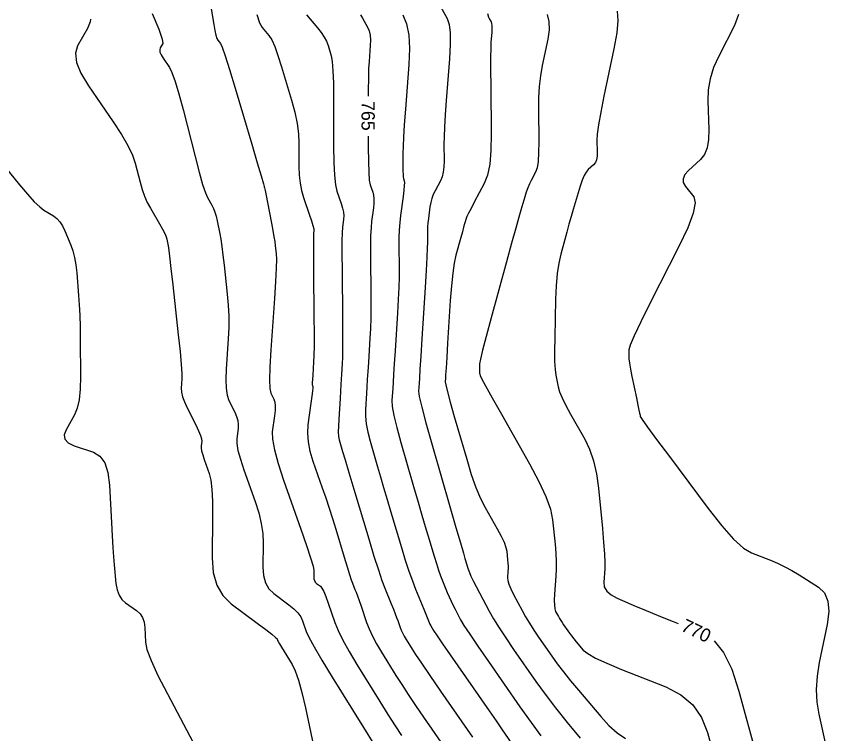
# Model space of a CAD drawing. Extents: x 2082232 to 2083549, y 592624 to 593832.
# Drawn here: x 2082859.4 to 2082902.15, y 592954.31 to 592992.08 of the extents above; entities that cross this region are included whole.
import ezdxf

# ---------------------------------------------------------------- set-up
doc = ezdxf.new("R2010")
doc.units = 0
doc.layers.add('DT_X_Contour_Major', color=7, linetype='Continuous')
doc.layers.add('DT_X_Contour_Minor', color=7, linetype='Continuous')

msp = doc.modelspace()

# ---------------------------------------------------------------- linework, layer by layer
at = {"layer": 'DT_X_Contour_Major'}
for points in [[(2082863.303, 592991.929), (2082863.288, 592991.791), (2082863.144, 592991.432), (2082862.623, 592990.518), (2082862.512, 592990.129), (2082862.572, 592989.649), (2082862.802, 592989.077), (2082863.203, 592988.414), (2082864.497, 592986.522), (2082864.934, 592985.854), (2082865.273, 592985.269), (2082865.516, 592984.767), (2082865.661, 592984.347), (2082865.918, 592983.339), (2082866.024, 592982.969), (2082866.151, 592982.618), (2082866.298, 592982.285), (2082866.465, 592981.97), (2082866.937, 592981.153), (2082867.094, 592980.873), (2082867.212, 592980.645), (2082867.29, 592980.47), (2082867.329, 592980.348), (2082867.379, 592980.092), (2082867.409, 592979.885), (2082867.462, 592979.457), (2082867.537, 592978.807), (2082867.635, 592977.936), (2082867.927, 592975.319), (2082868.021, 592974.437), (2082868.084, 592973.755), (2082868.118, 592973.272), (2082868.12, 592972.988), (2082868.087, 592972.499), (2082868.098, 592972.296), (2082868.153, 592972.056), (2082868.253, 592971.777), (2082868.399, 592971.461), (2082868.847, 592970.566), (2082868.992, 592970.261), (2082869.092, 592970.018), (2082869.148, 592969.836), (2082869.158, 592969.716), (2082869.125, 592969.476), (2082869.126, 592969.363), (2082869.155, 592969.203), (2082869.212, 592968.997), (2082869.295, 592968.744), (2082869.556, 592968.007), (2082869.64, 592967.661), (2082869.698, 592967.177), (2082869.729, 592966.554), (2082869.733, 592965.793), (2082869.707, 592963.578), (2082869.763, 592962.804), (2082869.949, 592962.141), (2082870.265, 592961.591), (2082870.712, 592961.154), (2082872.076, 592960.136), (2082872.525, 592959.798), (2082872.849, 592959.548), (2082873.048, 592959.385), (2082873.121, 592959.31), (2082873.15, 592959.225), (2082873.18, 592959.165), (2082873.247, 592959.048), (2082873.351, 592958.874), (2082873.493, 592958.644), (2082873.92, 592957.953), (2082874.084, 592957.617), (2082874.254, 592957.127), (2082874.431, 592956.482), (2082874.615, 592955.683), (2082875.114, 592953.345)], [(2082877.522, 592992.148), (2082877.626, 592991.972), (2082877.884, 592991.506), (2082877.966, 592991.315), (2082878.017, 592991.089), (2082878.038, 592990.829), (2082878.029, 592990.536), (2082877.965, 592989.707), (2082877.944, 592989.33), (2082877.929, 592988.823), (2082877.92, 592988.183), (2082877.919, 592987.871)], [(2082891.025, 592992.35), (2082891.055, 592991.864), (2082890.996, 592991.2), (2082890.846, 592990.358), (2082890.325, 592987.877), (2082890.156, 592987.033), (2082890.037, 592986.364), (2082889.969, 592985.869), (2082889.952, 592985.549), (2082889.976, 592984.927), (2082889.97, 592984.711), (2082889.935, 592984.528), (2082889.871, 592984.38), (2082889.778, 592984.265), (2082889.491, 592984.006), (2082889.384, 592983.879), (2082889.279, 592983.692), (2082889.175, 592983.447), (2082889.074, 592983.142), (2082888.805, 592982.251), (2082888.702, 592981.904), (2082888.595, 592981.533), (2082888.483, 592981.137), (2082888.367, 592980.717), (2082888.053, 592979.563), (2082887.948, 592979.089), (2082887.868, 592978.534), (2082887.812, 592977.898), (2082887.782, 592977.18), (2082887.734, 592975.157), (2082887.724, 592974.465), (2082887.73, 592973.905), (2082887.753, 592973.478), (2082887.792, 592973.184), (2082887.918, 592972.577), (2082887.994, 592972.316), (2082888.128, 592971.988), (2082888.32, 592971.595), (2082888.57, 592971.135), (2082889.315, 592969.82), (2082889.569, 592969.289), (2082889.773, 592968.681), (2082889.927, 592967.997), (2082890.031, 592967.237), (2082890.242, 592965.109), (2082890.309, 592964.377), (2082890.351, 592963.78), (2082890.369, 592963.317), (2082890.363, 592962.988), (2082890.312, 592962.289), (2082890.343, 592962.039), (2082890.471, 592961.815), (2082890.698, 592961.617), (2082891.024, 592961.444), (2082892.022, 592961.016), (2082892.424, 592960.846), (2082892.881, 592960.657), (2082893.392, 592960.449), (2082893.959, 592960.222), (2082894.238, 592960.11)], [(2082877.919, 592985.771), (2082877.92, 592985.181), (2082877.927, 592984.43), (2082877.947, 592983.852), (2082877.979, 592983.446), (2082878.023, 592983.213), (2082878.158, 592982.821), (2082878.198, 592982.659), (2082878.217, 592982.467), (2082878.214, 592982.244), (2082878.19, 592981.992), (2082878.097, 592981.278), (2082878.068, 592980.956), (2082878.048, 592980.528), (2082878.039, 592979.993), (2082878.04, 592979.351), (2082878.057, 592977.497), (2082878.059, 592976.828), (2082878.052, 592976.212), (2082878.035, 592975.649), (2082878.01, 592975.138), (2082877.929, 592973.849), (2082877.9, 592973.385), (2082877.873, 592972.961), (2082877.848, 592972.577), (2082877.826, 592972.233), (2082877.769, 592971.369), (2082877.769, 592971.023), (2082877.81, 592970.631), (2082877.893, 592970.195), (2082878.018, 592969.714), (2082878.406, 592968.371), (2082878.559, 592967.843), (2082878.728, 592967.267), (2082878.913, 592966.643), (2082879.114, 592965.97), (2082879.671, 592964.112), (2082879.873, 592963.453), (2082880.064, 592962.869), (2082880.243, 592962.361), (2082880.41, 592961.928), (2082880.839, 592960.873), (2082880.983, 592960.52), (2082881.093, 592960.256), (2082881.168, 592960.078), (2082881.21, 592959.988), (2082881.277, 592959.863), (2082881.355, 592959.741), (2082881.541, 592959.467), (2082881.835, 592959.041), (2082882.236, 592958.464), (2082883.448, 592956.722), (2082883.885, 592956.094), (2082884.285, 592955.519), (2082884.648, 592954.995), (2082884.975, 592954.522), (2082885.799, 592953.331)], [(2082896.121, 592959.205), (2082896.608, 592958.596), (2082897.049, 592957.708), (2082897.429, 592956.56), (2082898.359, 592953.15)]]:
    msp.add_lwpolyline(points, dxfattribs=at)
at = {"layer": 'DT_X_Contour_Minor'}
for points in [[(2082869.646, 592992.579), (2082869.791, 592991.644), (2082869.845, 592991.33), (2082869.899, 592991.087), (2082869.953, 592990.916), (2082870.006, 592990.817), (2082870.149, 592990.649), (2082870.236, 592990.455), (2082870.393, 592989.999), (2082870.619, 592989.281), (2082870.914, 592988.302), (2082871.792, 592985.341), (2082872.08, 592984.369), (2082872.286, 592983.675), (2082872.41, 592983.257), (2082872.452, 592983.117), (2082872.453, 592983.112), (2082872.453, 592983.11), (2082872.454, 592983.109), (2082872.454, 592983.108), (2082872.454, 592983.108), (2082872.454, 592983.108), (2082872.464, 592983.056), (2082872.495, 592982.901), (2082872.545, 592982.643), (2082872.616, 592982.282), (2082872.832, 592981.181), (2082872.905, 592980.799), (2082872.963, 592980.478), (2082873.005, 592980.219), (2082873.031, 592980.021), (2082873.081, 592979.575), (2082873.089, 592979.302), (2082873.075, 592978.817), (2082873.039, 592978.122), (2082872.982, 592977.215), (2082872.8, 592974.516), (2082872.748, 592973.615), (2082872.729, 592972.936), (2082872.742, 592972.48), (2082872.788, 592972.245), (2082872.953, 592971.916), (2082873.001, 592971.768), (2082873.024, 592971.574), (2082873.02, 592971.332), (2082872.99, 592971.043), (2082872.875, 592970.208), (2082872.88, 592969.813), (2082872.981, 592969.256), (2082873.177, 592968.536), (2082873.47, 592967.653), (2082874.378, 592965.082), (2082874.676, 592964.223), (2082874.889, 592963.574), (2082875.016, 592963.136), (2082875.057, 592962.909), (2082875.053, 592962.582), (2082875.062, 592962.468), (2082875.089, 592962.371), (2082875.136, 592962.29), (2082875.201, 592962.225), (2082875.402, 592962.075), (2082875.485, 592961.978), (2082875.581, 592961.799), (2082875.691, 592961.538), (2082875.816, 592961.195), (2082876.166, 592960.172), (2082876.337, 592959.745), (2082876.587, 592959.233), (2082876.918, 592958.635), (2082877.328, 592957.951), (2082878.527, 592956.014), (2082878.954, 592955.332), (2082879.332, 592954.737), (2082879.664, 592954.229)], [(2082881.721, 592992.589), (2082882.067, 592991.962), (2082882.173, 592991.654), (2082882.23, 592991.199), (2082882.239, 592990.596), (2082882.199, 592989.846), (2082882.028, 592987.65), (2082881.973, 592986.888), (2082881.934, 592986.25), (2082881.913, 592985.736), (2082881.908, 592985.345), (2082881.918, 592984.467), (2082881.908, 592984.155), (2082881.871, 592983.876), (2082881.808, 592983.63), (2082881.717, 592983.419), (2082881.439, 592982.899), (2082881.344, 592982.7), (2082881.268, 592982.491), (2082881.21, 592982.274), (2082881.171, 592982.047), (2082881.091, 592981.43), (2082881.064, 592981.206), (2082881.046, 592980.997), (2082881.036, 592980.803), (2082881.034, 592980.623), (2082881.038, 592980.162), (2082881.031, 592979.885), (2082881.009, 592979.398), (2082880.97, 592978.701), (2082880.914, 592977.795), (2082880.745, 592975.099), (2082880.688, 592974.195), (2082880.645, 592973.505), (2082880.615, 592973.028), (2082880.598, 592972.766), (2082880.571, 592972.352), (2082880.607, 592972.061), (2082880.734, 592971.501), (2082880.954, 592970.67), (2082881.265, 592969.569), (2082882.217, 592966.273), (2082882.534, 592965.175), (2082882.771, 592964.355), (2082882.929, 592963.812), (2082883.007, 592963.546), (2082883.109, 592963.206), (2082883.146, 592963.086), (2082883.181, 592962.979), (2082883.214, 592962.886), (2082883.244, 592962.807), (2082883.322, 592962.614), (2082883.373, 592962.505), (2082883.464, 592962.322), (2082883.597, 592962.066), (2082883.771, 592961.737), (2082884.29, 592960.76), (2082884.516, 592960.36), (2082884.804, 592959.893), (2082885.154, 592959.358), (2082885.565, 592958.756), (2082886.745, 592957.061), (2082887.223, 592956.398), (2082887.77, 592955.68), (2082888.387, 592954.909), (2082889.073, 592954.082)], [(2082866.557, 592992.224), (2082866.898, 592991.407), (2082867.082, 592990.882), (2082867.11, 592990.648), (2082866.976, 592990.414), (2082866.948, 592990.314), (2082866.963, 592990.191), (2082867.022, 592990.044), (2082867.125, 592989.874), (2082867.457, 592989.389), (2082867.596, 592989.114), (2082867.762, 592988.653), (2082867.956, 592988.005), (2082868.179, 592987.171), (2082868.809, 592984.699), (2082869.027, 592983.869), (2082869.208, 592983.232), (2082869.352, 592982.789), (2082869.459, 592982.539), (2082869.696, 592982.13), (2082869.779, 592981.964), (2082869.853, 592981.773), (2082869.918, 592981.557), (2082869.972, 592981.315), (2082870.105, 592980.636), (2082870.157, 592980.342), (2082870.212, 592979.968), (2082870.271, 592979.513), (2082870.333, 592978.979), (2082870.504, 592977.447), (2082870.555, 592976.869), (2082870.58, 592976.286), (2082870.578, 592975.697), (2082870.551, 592975.102), (2082870.444, 592973.508), (2082870.423, 592972.956), (2082870.441, 592972.496), (2082870.498, 592972.128), (2082870.593, 592971.853), (2082870.9, 592971.241), (2082870.997, 592971.015), (2082871.058, 592970.796), (2082871.084, 592970.584), (2082871.074, 592970.379), (2082871, 592969.842), (2082871.003, 592969.588), (2082871.068, 592969.23), (2082871.194, 592968.767), (2082871.383, 592968.199), (2082871.967, 592966.544), (2082872.158, 592965.942), (2082872.293, 592965.375), (2082872.372, 592964.845), (2082872.395, 592964.351), (2082872.38, 592963.08), (2082872.412, 592962.636), (2082872.519, 592962.256), (2082872.7, 592961.941), (2082872.957, 592961.69), (2082873.739, 592961.106), (2082874.005, 592960.888), (2082874.215, 592960.674), (2082874.37, 592960.462), (2082874.468, 592960.252), (2082874.658, 592959.698), (2082874.797, 592959.392), (2082875.073, 592958.889), (2082875.484, 592958.19), (2082876.032, 592957.293), (2082877.675, 592954.641), (2082878.223, 592953.757)], [(2082872.068, 592992.169), (2082872.204, 592991.737), (2082872.339, 592991.487), (2082872.699, 592991.062), (2082872.841, 592990.84), (2082872.999, 592990.493), (2082873.172, 592990.02), (2082873.36, 592989.422), (2082873.883, 592987.661), (2082874.054, 592987.024), (2082874.177, 592986.437), (2082874.25, 592985.899), (2082874.275, 592985.41), (2082874.276, 592984.171), (2082874.292, 592983.721), (2082874.337, 592983.3), (2082874.412, 592982.908), (2082874.517, 592982.546), (2082874.837, 592981.618), (2082874.941, 592981.306), (2082875.013, 592981.066), (2082875.054, 592980.897), (2082875.062, 592980.8), (2082875.041, 592980.638), (2082875.035, 592980.47), (2082875.033, 592980.088), (2082875.035, 592979.492), (2082875.042, 592978.682), (2082875.064, 592976.238), (2082875.069, 592975.403), (2082875.068, 592974.733), (2082875.06, 592974.226), (2082875.046, 592973.885), (2082874.999, 592973.192), (2082874.985, 592972.962), (2082874.978, 592972.793), (2082874.976, 592972.685), (2082874.982, 592972.637), (2082875.005, 592972.59), (2082875.006, 592972.522), (2082874.989, 592972.352), (2082874.956, 592972.08), (2082874.906, 592971.706), (2082874.75, 592970.574), (2082874.722, 592970.136), (2082874.756, 592969.672), (2082874.851, 592969.182), (2082875.007, 592968.666), (2082875.505, 592967.255), (2082875.69, 592966.723), (2082875.869, 592966.183), (2082876.043, 592965.637), (2082876.213, 592965.084), (2082876.657, 592963.6), (2082876.809, 592963.097), (2082876.932, 592962.703), (2082877.026, 592962.418), (2082877.09, 592962.241), (2082877.223, 592961.914), (2082877.281, 592961.766), (2082877.353, 592961.569), (2082877.441, 592961.322), (2082877.543, 592961.025), (2082877.836, 592960.168), (2082877.968, 592959.83), (2082878.143, 592959.457), (2082878.361, 592959.05), (2082878.623, 592958.609), (2082879.38, 592957.387), (2082879.684, 592956.906), (2082880.028, 592956.378), (2082880.413, 592955.804), (2082880.837, 592955.184), (2082882.024, 592953.467)], [(2082874.672, 592992.158), (2082875.249, 592991.476), (2082875.446, 592991.226), (2082875.604, 592990.988), (2082875.724, 592990.762), (2082875.805, 592990.547), (2082875.97, 592989.991), (2082876.024, 592989.692), (2082876.063, 592989.213), (2082876.087, 592988.553), (2082876.095, 592987.714), (2082876.098, 592985.234), (2082876.109, 592984.389), (2082876.142, 592983.715), (2082876.195, 592983.212), (2082876.27, 592982.879), (2082876.498, 592982.22), (2082876.57, 592981.983), (2082876.615, 592981.766), (2082876.634, 592981.571), (2082876.626, 592981.396), (2082876.569, 592980.958), (2082876.551, 592980.694), (2082876.541, 592980.233), (2082876.539, 592979.573), (2082876.544, 592978.715), (2082876.567, 592976.164), (2082876.573, 592975.299), (2082876.574, 592974.619), (2082876.568, 592974.122), (2082876.557, 592973.81), (2082876.521, 592973.224), (2082876.505, 592972.98), (2082876.487, 592972.689), (2082876.465, 592972.352), (2082876.44, 592971.967), (2082876.368, 592970.878), (2082876.35, 592970.503), (2082876.348, 592970.197), (2082876.363, 592969.958), (2082876.394, 592969.786), (2082876.5, 592969.42), (2082876.572, 592969.177), (2082876.707, 592968.723), (2082876.905, 592968.059), (2082877.167, 592967.183), (2082877.951, 592964.566), (2082878.224, 592963.668), (2082878.455, 592962.938), (2082878.644, 592962.376), (2082878.792, 592961.982), (2082879.128, 592961.155), (2082879.244, 592960.867), (2082879.34, 592960.623), (2082879.416, 592960.424), (2082879.471, 592960.268), (2082879.593, 592959.913), (2082879.647, 592959.773), (2082879.72, 592959.618), (2082879.811, 592959.449), (2082879.919, 592959.267), (2082880.233, 592958.76), (2082880.414, 592958.481), (2082880.724, 592958.02), (2082881.161, 592957.38), (2082881.727, 592956.559), (2082883.406, 592954.13)], [(2082879.748, 592992.147), (2082879.938, 592991.676), (2082880.054, 592991.086), (2082880.096, 592990.377), (2082880.064, 592989.549), (2082879.88, 592987.181), (2082879.82, 592986.371), (2082879.777, 592985.717), (2082879.751, 592985.219), (2082879.743, 592984.876), (2082879.743, 592984.17), (2082879.746, 592983.932), (2082879.752, 592983.749), (2082879.762, 592983.621), (2082879.776, 592983.547), (2082879.819, 592983.423), (2082879.827, 592983.336), (2082879.819, 592983.168), (2082879.794, 592982.918), (2082879.754, 592982.588), (2082879.626, 592981.598), (2082879.584, 592981.218), (2082879.555, 592980.824), (2082879.54, 592980.413), (2082879.537, 592979.987), (2082879.548, 592978.829), (2082879.545, 592978.356), (2082879.53, 592977.805), (2082879.502, 592977.175), (2082879.462, 592976.467), (2082879.337, 592974.474), (2082879.294, 592973.79), (2082879.259, 592973.233), (2082879.232, 592972.803), (2082879.212, 592972.5), (2082879.17, 592971.861), (2082879.188, 592971.542), (2082879.272, 592971.066), (2082879.423, 592970.433), (2082879.641, 592969.641), (2082880.311, 592967.322), (2082880.547, 592966.509), (2082880.75, 592965.811), (2082880.921, 592965.227), (2082881.061, 592964.758), (2082881.39, 592963.659), (2082881.51, 592963.269), (2082881.622, 592962.924), (2082881.728, 592962.623), (2082881.827, 592962.367), (2082882.081, 592961.743), (2082882.178, 592961.513), (2082882.278, 592961.289), (2082882.383, 592961.072), (2082882.491, 592960.862), (2082882.783, 592960.312), (2082882.957, 592960.019), (2082883.259, 592959.555), (2082883.689, 592958.919), (2082884.247, 592958.111), (2082885.906, 592955.729), (2082886.491, 592954.899), (2082887, 592954.199)], [(2082884.19, 592992.218), (2082884.257, 592992.035), (2082884.3, 592991.935), (2082884.387, 592991.778), (2082884.413, 592991.701), (2082884.428, 592991.587), (2082884.43, 592991.437), (2082884.42, 592991.249), (2082884.377, 592990.701), (2082884.365, 592990.403), (2082884.359, 592989.921), (2082884.359, 592989.255), (2082884.367, 592988.405), (2082884.396, 592985.892), (2082884.38, 592985.022), (2082884.314, 592984.296), (2082884.195, 592983.713), (2082884.025, 592983.275), (2082883.503, 592982.297), (2082883.329, 592981.968), (2082883.199, 592981.714), (2082883.113, 592981.535), (2082883.071, 592981.431), (2082883.017, 592981.254), (2082882.988, 592981.152), (2082882.94, 592980.98), (2082882.873, 592980.738), (2082882.788, 592980.426), (2082882.536, 592979.5), (2082882.446, 592979.09), (2082882.367, 592978.556), (2082882.299, 592977.898), (2082882.241, 592977.116), (2082882.099, 592974.864), (2082882.053, 592974.116), (2082882.018, 592973.561), (2082881.995, 592973.2), (2082881.984, 592973.033), (2082881.972, 592972.843), (2082881.998, 592972.676), (2082882.087, 592972.314), (2082882.238, 592971.76), (2082882.451, 592971.011), (2082883.102, 592968.758), (2082883.345, 592967.966), (2082883.587, 592967.28), (2082883.827, 592966.701), (2082884.066, 592966.227), (2082884.7, 592965.106), (2082884.91, 592964.717), (2082885.066, 592964.39), (2082885.165, 592964.124), (2082885.21, 592963.92), (2082885.256, 592963.459), (2082885.27, 592963.292), (2082885.277, 592963.137), (2082885.278, 592962.994), (2082885.272, 592962.862), (2082885.248, 592962.527), (2082885.261, 592962.377), (2082885.319, 592962.179), (2082885.421, 592961.933), (2082885.568, 592961.639), (2082886.019, 592960.792), (2082886.2, 592960.466), (2082886.404, 592960.126), (2082886.632, 592959.771), (2082886.883, 592959.4), (2082887.584, 592958.393), (2082887.869, 592957.998), (2082888.198, 592957.567), (2082888.57, 592957.102), (2082888.985, 592956.602), (2082890.152, 592955.222), (2082890.588, 592954.748), (2082891.023, 592954.36), (2082891.456, 592954.059)], [(2082887.33, 592992.178), (2082887.426, 592991.802), (2082887.44, 592991.367), (2082887.372, 592990.873), (2082887.079, 592989.48), (2082886.985, 592988.944), (2082886.919, 592988.379), (2082886.882, 592987.787), (2082886.875, 592987.167), (2082886.894, 592985.475), (2082886.889, 592984.9), (2082886.861, 592984.441), (2082886.808, 592984.1), (2082886.731, 592983.875), (2082886.495, 592983.433), (2082886.408, 592983.255), (2082886.323, 592983.053), (2082886.24, 592982.827), (2082886.16, 592982.577), (2082885.948, 592981.877), (2082885.842, 592981.509), (2082885.68, 592980.932), (2082885.462, 592980.144), (2082885.19, 592979.146), (2082884.389, 592976.206), (2082884.126, 592975.228), (2082883.938, 592974.5), (2082883.824, 592974.022), (2082883.784, 592973.793), (2082883.777, 592973.517), (2082883.776, 592973.422), (2082883.777, 592973.346), (2082883.78, 592973.287), (2082883.785, 592973.247), (2082883.803, 592973.164), (2082883.878, 592973.014), (2082884.091, 592972.626), (2082884.441, 592972), (2082884.928, 592971.136), (2082886.412, 592968.515), (2082886.905, 592967.595), (2082887.27, 592966.798), (2082887.509, 592966.126), (2082887.621, 592965.579), (2082887.749, 592964.284), (2082887.788, 592963.815), (2082887.808, 592963.379), (2082887.811, 592962.976), (2082887.794, 592962.606), (2082887.727, 592961.664), (2082887.711, 592961.342), (2082887.716, 592961.083), (2082887.74, 592960.888), (2082887.783, 592960.755), (2082887.926, 592960.486), (2082887.984, 592960.383), (2082888.049, 592960.275), (2082888.121, 592960.162), (2082888.201, 592960.045), (2082888.423, 592959.725), (2082888.514, 592959.6), (2082888.618, 592959.463), (2082888.736, 592959.315), (2082888.868, 592959.157), (2082889.238, 592958.719), (2082889.468, 592958.532), (2082889.881, 592958.299), (2082890.477, 592958.021), (2082891.255, 592957.698), (2082893.574, 592956.774), (2082894.364, 592956.365), (2082894.994, 592955.83), (2082895.465, 592955.169), (2082895.776, 592954.382), (2082896.394, 592952.117)], [(2082897.409, 592992.171), (2082897.187, 592991.589), (2082896.364, 592989.976), (2082896.096, 592989.376), (2082895.911, 592988.784), (2082895.809, 592988.202), (2082895.789, 592987.628), (2082895.846, 592986.111), (2082895.834, 592985.586), (2082895.757, 592985.149), (2082895.615, 592984.799), (2082895.407, 592984.538), (2082894.767, 592983.958), (2082894.577, 592983.743), (2082894.489, 592983.531), (2082894.501, 592983.323), (2082894.615, 592983.119), (2082895.055, 592982.58), (2082895.128, 592982.264), (2082895.021, 592981.721), (2082894.732, 592980.951), (2082894.261, 592979.953), (2082892.764, 592976.989), (2082892.273, 592976.002), (2082891.921, 592975.262), (2082891.708, 592974.771), (2082891.636, 592974.528), (2082891.628, 592974.209), (2082891.637, 592974.052), (2082891.668, 592973.818), (2082891.722, 592973.508), (2082891.798, 592973.122), (2082892.033, 592971.989), (2082892.11, 592971.617), (2082892.166, 592971.351), (2082892.2, 592971.19), (2082892.212, 592971.133), (2082892.218, 592971.124), (2082892.22, 592971.118), (2082892.222, 592971.107), (2082892.224, 592971.091), (2082892.226, 592971.069), (2082892.233, 592971.005), (2082892.33, 592970.856), (2082892.619, 592970.456), (2082893.098, 592969.806), (2082893.767, 592968.906), (2082895.808, 592966.171), (2082896.524, 592965.256), (2082897.143, 592964.561), (2082897.664, 592964.085), (2082898.087, 592963.831), (2082899.086, 592963.444), (2082899.462, 592963.288), (2082899.839, 592963.107), (2082900.217, 592962.902), (2082900.597, 592962.674), (2082901.612, 592962.033), (2082901.926, 592961.73), (2082902.106, 592961.299), (2082902.153, 592960.742), (2082902.065, 592960.059), (2082901.653, 592958.066), (2082901.536, 592957.335), (2082901.493, 592956.636), (2082901.523, 592955.969), (2082901.628, 592955.335), (2082902.006, 592953.684)], [(2082858.337, 592984.7), (2082859.567, 592983.212), (2082859.994, 592982.71), (2082860.351, 592982.319), (2082860.64, 592982.04), (2082860.861, 592981.872), (2082861.356, 592981.573), (2082861.533, 592981.44), (2082861.693, 592981.264), (2082861.836, 592981.046), (2082861.962, 592980.786), (2082862.275, 592980.036), (2082862.382, 592979.734), (2082862.469, 592979.39), (2082862.536, 592979.004), (2082862.583, 592978.576), (2082862.68, 592977.379), (2082862.713, 592976.896), (2082862.738, 592976.345), (2082862.756, 592975.727), (2082862.766, 592975.041), (2082862.783, 592973.122), (2082862.767, 592972.455), (2082862.709, 592971.895), (2082862.608, 592971.443), (2082862.464, 592971.097), (2082862.023, 592970.316), (2082861.926, 592970.044), (2082861.965, 592969.813), (2082862.14, 592969.623), (2082862.452, 592969.474), (2082863.465, 592969.132), (2082863.803, 592968.927), (2082864.055, 592968.569), (2082864.222, 592968.058), (2082864.304, 592967.393), (2082864.41, 592965.417), (2082864.449, 592964.723), (2082864.487, 592964.123), (2082864.523, 592963.617), (2082864.558, 592963.204), (2082864.649, 592962.23), (2082864.706, 592961.891), (2082864.809, 592961.606), (2082864.956, 592961.375), (2082865.149, 592961.197), (2082865.724, 592960.795), (2082865.914, 592960.627), (2082866.052, 592960.424), (2082866.139, 592960.185), (2082866.174, 592959.912), (2082866.199, 592959.136), (2082866.278, 592958.748), (2082866.497, 592958.165), (2082866.854, 592957.387), (2082867.351, 592956.415), (2082868.861, 592953.562)]]:
    msp.add_lwpolyline(points, dxfattribs=at)

# ---------------------------------------------------------------- texts
at = {"layer": 'DT_X_Contour_Major'}
for s, rotation, p in [('765', 270.0042, (2082877.568, 592987.618)), ('770', 334.3309, (2082894.327, 592959.76))]:
    msp.add_text(s, height=0.7, rotation=rotation, dxfattribs=at).set_placement(p)

doc.saveas('drawing.dxf')
